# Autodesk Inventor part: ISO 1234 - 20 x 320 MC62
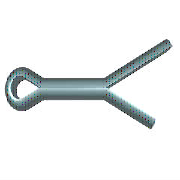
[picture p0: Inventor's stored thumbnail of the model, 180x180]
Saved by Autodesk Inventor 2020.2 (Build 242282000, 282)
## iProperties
Manager: www.cadconsulting.pl
Company: Fabian Stasiak CAD Consulting
Created: 2010-10
Part Number: ISO 1234 - 20 x 320 MC62
Material: Mosiądz, jasnożółty
Description: Zawleczka
Document SubType Name: Modeling
Standard: ISO 1234
Designer: F.Stasiak
Standard Revision: Second edition 1997-11-01
Standards Organization: ISO
Language: pl-PL
Size Designation: 20 x 320
Categories: <MemberInstance><Categories><Category DisplayName="Mocowania" InternalName="e4da775c-781d-43d5-af7c-5136215cf5a6" Mnemonic="FSTN"><Category DisplayName="Kołki"
Density: 8.47 g/cm^3
Appearance: Metal-Mosiądz
IsCustomPart: 0
Author: F.Stasiak
Subject: Zbiór ćwiczeń. Autodesk Inventor 2020. Kurs podstawowy
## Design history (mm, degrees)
sketch "Sketch1"
  geometry: L1 (0, 9.65)-(248, 9.65); L2 (0, -9.65)-(248, -9.65); L3 (248, 9.65)-(320, 37.235); L4 (320, 37.235)-(323.224, 28.82); L5 (323.224, 28.82)-(248, 0); L6 (248, 0)-(329.524, -31.233); L7 (329.524, -31.233)-(326.3, -39.648); L8 (326.3, -39.648)-(248, -9.65); L9 (0, 0)-(-16.309, -8.511); L10 (0, 0)-(-16.309, 8.511); L11 (0, 9.65)-(0, -9.65); L12 (0, 9.65)-(-10.457, 16.267); L13 (0, -9.65)-(-10.457, -16.267); L14 (-40, 0)-(248, 0); L15 (248, 9.65)-(248, -9.65); A1 r 19.25 centre (-20.75, 0) between (-10.457, 16.267) and (-10.457, -16.267); A2 r 9.6 centre (-20.75, 0) between (-16.309, 8.511) and (-16.309, -8.511); 1 further point
  constraints: 30 end point, 5 point on circle, 4 parallel, 4 perpendicular, 4 point on line, 4 tangent, 2 centre point, 2 midpoint, 1 coincident, 1 horizontal
  dimensions: "d0" = 248 distance of L1.start L1.end (= MSIAB); "d1" = 320 horizontal distance of L1.start L3.end (= SNLG); "d2" = 159.037 deg angle of L1 L3; "d3" = 159.037 deg angle of L2 L8; "d4" = 6.3 horizontal distance of L3.end L7.end (= LGDIF); "d5" = 9.6 radius of A2 (= -0.5 x SNND1 + 0.5 x KBR); "d6" = 19.25 radius of A1 (= 0.5 x KBR); "d7" = 9.65 distance from line of L1 L9.start (= 0.5 x SNND1); "d8" = 9.65 distance between parallel lines of L2 L14 (= 0.5 x SNND1); "d9" = 20.75 distance from line of L11 A1.centre (= KOL - 0.5 x KBR)
extrude "Body" new body sketch "Sketch1" stored distance "d10" = 19.3 (= SNND1); taper "d11" = 0 deg
fillet "Fillet" dims "d12" = 6.755 (= 0.35 x SNND1)
workaxis "Work Axis1"
workplane "Work Plane1"
workplane "Work Plane3"
body "Solid1"
other parameters: "SNLG" = 320 [user parameter; used in 1 equation term], "SNND1" = 19.3 [user parameter; used in 5 equation terms], "KBR" = 38.5 [user parameter; used in 3 equation terms], "LGDIF" = 6.3 [user parameter; used in 1 equation term], "MSIAB" = 248 [user parameter; used in 1 equation term], "d15" = 0, "d16" = 0, "d17" = 0, "DSH" = 26 [user parameter]
